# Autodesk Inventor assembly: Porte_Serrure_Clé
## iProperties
Created: 2009-01
Part Number: Porte_Serrure_Clé
Document SubType Name: Assembly
Designer: claivier
Norme de conversion: STEP AP214IS
Nom du fichier: SW3dPS-93-10-101-10.STEP
Préprocesseur: SolidWorks 2008
Postprocesseur: Build: 344a, Release: 11 SP2 - Date: Fri 08/18/2006
Unités envoyées: INCHES
Incertitude: 1e-05
Author: claivier
